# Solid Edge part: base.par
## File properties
Title: Base
Author: Deepak Maini
Template: Normal.par
Last saved by: Robert a Rhodes jr
Revision: 22
Application: Solid Edge
Material: aluminum
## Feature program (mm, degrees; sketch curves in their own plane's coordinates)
sketch for "unnamed Protrusion 1" plane through (0, 0, 0) normal (1, 0, 0) x-axis (0, 1, 0)
  line (-34.925, 42.0624) -> (-34.925, -42.0624)
  line (-15.875, -42.0624) -> (-34.925, -42.0624)
  line (-15.875, -42.0624) -> (-15.875, -15.0876)
  line (-15.875, -15.0876) -> (-12.7, -15.0876)
  line (-12.7, -15.0876) -> (-12.7, 0.8001)
  line (-12.7, 0.8001) -> (12.7, 0.8001)
  line (12.7, 0.8001) -> (12.7, -15.0876)
  line (12.7, -15.0876) -> (15.875, -15.0876)
  line (15.875, -15.0876) -> (15.875, -42.0624)
  line (15.875, -42.0624) -> (34.925, -42.0624)
  line (34.925, -42.0624) -> (34.925, 42.0624)
  line (34.925, 42.0624) -> (-34.925, 42.0624)
  dimension (linear) = 15.875
extrude "unnamed Protrusion 1" add finite 184.15 along -normal
sketch for "unnamed Cutout 1" plane through (-92.075, -34.925, 0) normal (0, -1, 0) x-axis (1, 0, 0)
  line (-60.325, 58.9033) -> (-60.325, -2.3876)
  line (-60.325, -2.3876) -> (66.675, -2.3876)
  line (66.675, -2.3876) -> (66.675, 32.5374)
  line (66.675, 32.5374) -> (138.7184, 32.5374)
  line (138.7184, 32.5374) -> (138.7184, 58.9033)
  line (-60.325, 58.9033) -> (138.7184, 58.9033)
extrude "unnamed Cutout 1" cut through along -normal
sketch for "unnamed Cutout 2" plane through (0, 0, -4.3434) normal (1, 0, 0) x-axis (0, 1, 0)
  line (18.2179, 17.8308) -> (34.925, 17.8308)
  line (42.2755, 17.8308) -> (34.925, 17.8308)
  line (42.2755, 51.2375) -> (42.2755, 17.8308)
  line (-47.5259, 51.2375) -> (42.2755, 51.2375)
  line (-47.5259, 17.8308) -> (-47.5259, 51.2375)
  line (-34.925, 17.8308) -> (-47.5259, 17.8308)
  line (-34.925, 17.8308) -> (-18.2179, 17.8308)
  arc centre (0, 18.6448) radius 18.236 from (-18.2179, 17.8308) to (18.2179, 17.8308) cw
extrude "unnamed Cutout 2" cut finite 76.2 along -normal
sketch for "unnamed Hole 1" plane through (0, 0, -4.7625) normal (1, 0, 0) x-axis (0, 1, 0)
  hole centre (0, 19.0639) bore radius 7.9375
hole "unnamed Hole 1" through
fillet "unnamed Round 1"
sketch for "unnamed Protrusion 2" plane through (-92.075, -25.4, -42.0624) normal (0, 0, -1) x-axis (1, 0, 0)
  arc centre (63.5638, -62.2328) radius 28.575 from (92.075, -60.325) to (35.0525, -60.325) cw
  line (35.4, -60.325) -> (92.075, -60.325)
extrude "unnamed Protrusion 2" add finite 7.9248 along -normal
sketch for "unnamed Hole 2" plane through (-31.5444, 50.1664, -34.1376) normal (0, 0, 1) x-axis (-1, 0, 0)
hole "unnamed Hole 2" through
mirror "unnamed Mirror 1" of "unnamed Protrusion 2", "unnamed Hole 2" about plane through (-92.075, 0, 0) normal (1, 0, 0)
extrude "unnamed Protrusion 3" add finite 7.9248
hole "unnamed Hole 3" through
mirror "unnamed Mirror 2" of "unnamed Protrusion 2", "unnamed Hole 2", "unnamed Mirror 1" about plane through (0, 0, 0) normal (0, -1, 0)
extrude "unnamed Protrusion 4" add finite 7.9248
hole "unnamed Hole 4" through
extrude "unnamed Protrusion 5" add finite 7.9248
hole "unnamed Hole 5" through
sketch for "unnamed Hole 6" plane through (-152.4, 0, 15.5518) normal (1, 0, 0) x-axis (0, 1, 0)
  hole centre (19.05, 7.4606) bore radius 3.175
hole "unnamed Hole 6" finite
sketch for "unnamed Hole 7" plane through (-152.4, 0, 15.5518) normal (1, 0, 0) x-axis (0, 1, 0)
  hole centre (-19.05, 7.4606) bore radius 3.175
  dimension (linear) = 19.05
  dimension (linear) = 19.05
hole "unnamed Hole 7" finite
pattern "unnamed Pattern 1" of "unnamed Hole 6", "unnamed Hole 7"
fillet "unnamed Round 2"
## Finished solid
Body 1: solid body, 88 faces, 215 edges, 122 vertices.
  Faces by surface: cylinder 35, plane 26, torus 13, blend 12, sphere 2
  Edges by curve: line 96, circle 93, intersection 26
Bounding box of the edges (mm; curved faces can reach further): 184.280 x 130.816 x 84.125, from (-184.2151, -65.4078, -42.0624) to (0.0651, 65.4078, 42.0624).
Cylindrical faces by radius (mm): R3.175 x2, R3.81 x22, R3.9624 x4, R7.9375 x1, R18.236 x1, R28.575 x4, R34.925 x1
Toroidal faces (ring radius, tube radius in mm): R7.62 r3.81 x6, R14.426 r3.81 x1, R24.765 r3.81 x4, R31.115 r3.81 x2
Spherical faces by radius (mm): R3.81 x2
Planar faces by outward normal: +x 4, +y 3, +z 8, -x 2, -y 3, -z 6
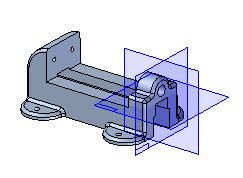
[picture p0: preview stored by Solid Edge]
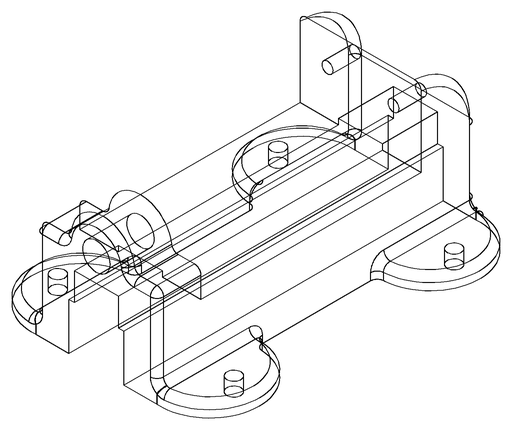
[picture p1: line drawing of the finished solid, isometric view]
